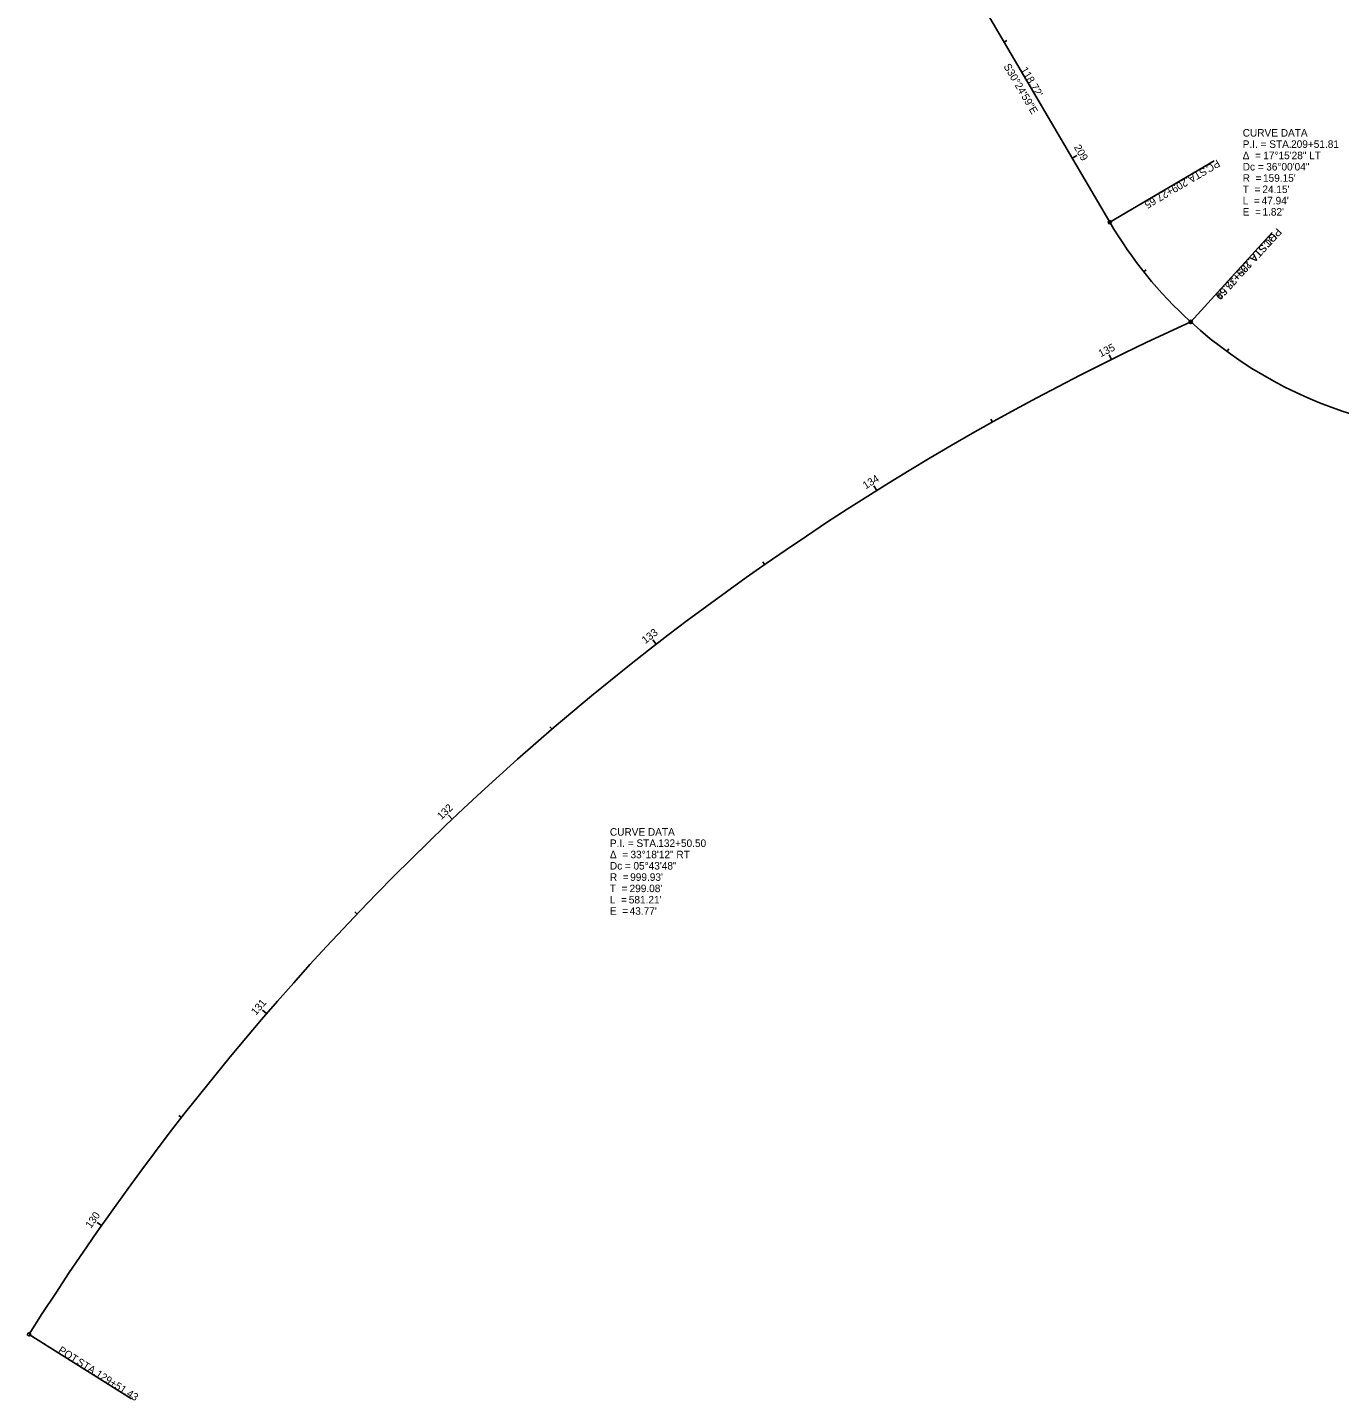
# Model space of a CAD drawing. Extents: x 1926907 to 1928253, y 199360 to 200380.
# Drawn here: x 1927233 to 1927721, y 199360 to 199871 of the extents above; entities that cross this region are included whole.
import ezdxf

# ---------------------------------------------------------------- set-up
doc = ezdxf.new("R2010")
doc.units = 0
for name, color, linetype in [('RW_X_CL', 7, 'Continuous'), ('RW_X_CL_100_Bearings', 7, 'Continuous'), ('RW_X_CL_100_Cardinal_Points', 7, 'Continuous'), ('RW_X_CL_100_Curve_Data', 7, 'Continuous'), ('RW_X_CL_100_Distances', 7, 'Continuous'), ('RW_X_CL_100_Stations', 7, 'Continuous')]:
    doc.layers.add(name, color=color, linetype=linetype)

msp = doc.modelspace()

# ---------------------------------------------------------------- linework, layer by layer
at = {"layer": 'RW_X_CL'}
msp.add_line((1927574.99, 199900.83), (1927635.1, 199798.45), dxfattribs=at)
for centre, radius, start, end in [((1927772.34, 199879.02), 159.15, 210.4164, 227.6743), ((1928078.57, 198850.88), 999.93, 114.41943, 147.7229), ((1927772.34, 199879.02), 159.15, 227.6743, 282.0514)]:
    msp.add_arc(centre, radius, start, end, dxfattribs=at)
at = {"layer": 'RW_X_CL_100_Cardinal_Points'}
for p, q in [((1927635.1, 199798.45), (1927673.9, 199821.23)), ((1927665.18, 199761.36), (1927695.48, 199794.63)), ((1927665.18, 199761.36), (1927695.48, 199794.63)), ((1927233.15, 199384.85), (1927271.2, 199360.82))]:
    msp.add_line(p, q, dxfattribs=at)
for centre in [(1927635.1, 199798.45), (1927665.18, 199761.36), (1927665.18, 199761.36), (1927233.15, 199384.85)]:
    msp.add_circle(centre, 0.6, dxfattribs=at)
at = {"layer": 'RW_X_CL_100_Stations'}
for p, q in [((1927595.78, 199865.41), (1927596.82, 199866.02)), ((1927621.1, 199822.29), (1927622.82, 199823.31)), ((1927647.72, 199780.03), (1927648.66, 199780.78)), ((1927635.69, 199747.38), (1927634.8, 199749.17)), ((1927678.63, 199750.39), (1927679.33, 199751.36)), ((1927591.43, 199724.12), (1927590.84, 199725.17)), ((1927548.39, 199698.68), (1927547.33, 199700.38)), ((1927506.68, 199671.12), (1927505.99, 199672.11)), ((1927466.39, 199641.51), (1927465.17, 199643.1)), ((1927427.64, 199609.93), (1927426.86, 199610.84)), ((1927390.52, 199576.44), (1927389.14, 199577.9)), ((1927355.11, 199541.15), (1927354.24, 199541.98)), ((1927321.51, 199504.12), (1927320, 199505.43)), ((1927289.81, 199465.47), (1927288.86, 199466.21)), ((1927260.08, 199425.28), (1927258.44, 199426.42))]:
    msp.add_line(p, q, dxfattribs=at)

# ---------------------------------------------------------------- texts
at = {"layer": 'RW_X_CL_100_Bearings'}
msp.add_text('S30°24\'59"E', height=2.8, rotation=300.4164, dxfattribs=at).set_placement((1927595.48, 199856.44))
at = {"layer": 'RW_X_CL_100_Cardinal_Points'}
for s, rotation, p in [('PC', 210.4164, (1927675.02, 199821.84)), (' STA. ', 210.4164, (1927671.06, 199819.51)), ('209+27.65', 210.4164, (1927663.02, 199814.79)), ('PRC', 227.6743, (1927697.19, 199796.45)), ('POT', 227.6743, (1927697.23, 199796.49)), (' STA. ', 227.6743, (1927692.43, 199791.22)), (' STA. ', 227.6743, (1927692.54, 199791.34)), ('209+75.59', 227.6743, (1927686.15, 199784.33)), ('135+32.64', 227.6743, (1927686.27, 199784.45)), ('POT', 327.7229, (1927243.71, 199378.23)), (' STA. ', 327.7229, (1927249.74, 199374.42)), ('129+51.43', 327.7229, (1927257.62, 199369.44))]:
    msp.add_text(s, height=2.8, rotation=rotation, dxfattribs=at).set_placement(p)
at = {"layer": 'RW_X_CL_100_Curve_Data'}
for s, p in [('CURVE DATA', (1927684.51, 199830.29)), ('P.I. = STA. ', (1927684.51, 199826.09)), ('209+51.81', (1927702.5, 199826.09)), ('Δ  = ', (1927684.51, 199821.89)), ('17°15\'28" LT', (1927692.16, 199821.89)), ('36°00\'04"', (1927693.26, 199817.69)), ('Dc = ', (1927684.51, 199817.69)), ('R  = ', (1927684.51, 199813.49)), ("159.15'", (1927692.05, 199813.49)), ('T  = ', (1927684.51, 199809.29)), ("24.15'", (1927691.83, 199809.29)), ('L  = ', (1927684.51, 199805.09)), ("47.94'", (1927691.55, 199805.09)), ('E  = ', (1927684.51, 199800.89)), ("1.82'", (1927691.85, 199800.89)), ('CURVE DATA', (1927449.16, 199570.3)), ('P.I. = STA. ', (1927449.16, 199566.1)), ('132+50.50', (1927467.16, 199566.1)), ('Δ  = ', (1927449.16, 199561.9)), ('Dc = ', (1927449.16, 199557.7)), ('33°18\'12" RT', (1927456.81, 199561.9)), ('05°43\'48"', (1927457.91, 199557.7)), ('R  = ', (1927449.16, 199553.5)), ("999.93'", (1927456.7, 199553.5)), ('T  = ', (1927449.16, 199549.3)), ("299.08'", (1927456.48, 199549.3)), ('L  = ', (1927449.16, 199545.1)), ("581.21'", (1927456.2, 199545.1)), ('E  = ', (1927449.16, 199540.9)), ("43.77'", (1927456.51, 199540.9))]:
    msp.add_text(s, height=2.8, dxfattribs=at).set_placement(p)
at = {"layer": 'RW_X_CL_100_Distances'}
msp.add_text("118.72'", height=2.8, rotation=300.4164, dxfattribs=at).set_placement((1927601.82, 199855.21))
at = {"layer": 'RW_X_CL_100_Stations'}
for s, rotation, p in [('209', 300.4164, (1927621.62, 199826.34)), ('135', 26.2897, (1927631.7, 199748.2)), ('134', 32.0197, (1927544.28, 199699.06)), ('133', 37.7497, (1927462.34, 199641.53)), ('132', 43.4797, (1927386.47, 199576.05)), ('131', 49.2096, (1927317.51, 199503.32)), ('130', 54.9396, (1927256.15, 199424.04))]:
    msp.add_text(s, height=2.8, rotation=rotation, dxfattribs=at).set_placement(p)

doc.saveas('drawing.dxf')
